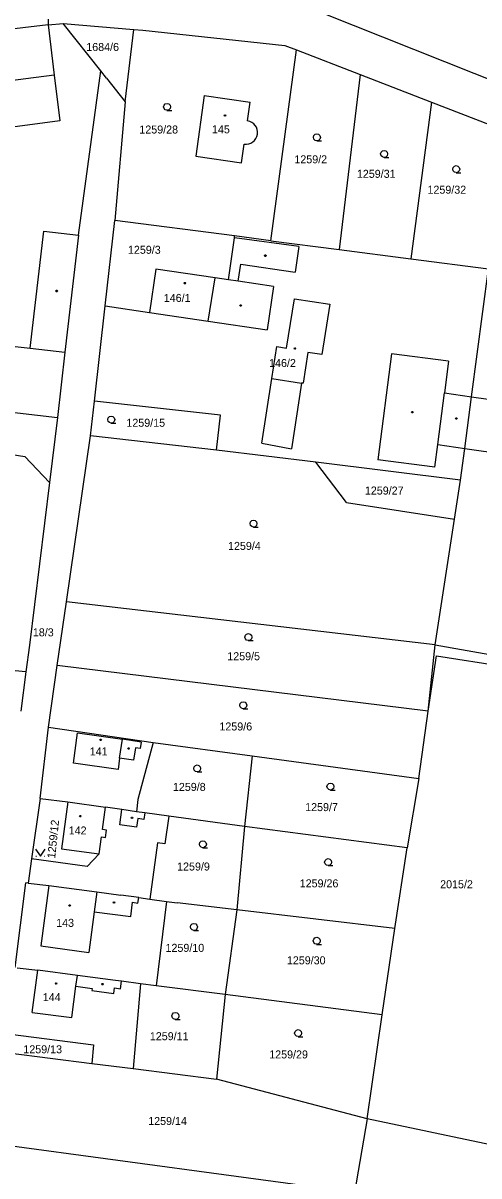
# Model space of a CAD drawing. Extents: x -802857 to -799647, y -1020285 to -1015884.
# Drawn here: x -801322.5 to -801225.7, y -1017885.2 to -1017640.2 of the extents above; entities that cross this region are included whole.
import ezdxf

# ---------------------------------------------------------------- set-up
doc = ezdxf.new("R2010")
doc.units = 0
for name, color, linetype in [('Default', 7, 'Continuous'), ('KN_HRANICE', 7, 'Continuous'), ('KN_KULTURY', 7, 'Continuous'), ('KN_PARCELY', 7, 'Continuous'), ('KN_SLUCKY', 7, 'Continuous')]:
    doc.layers.add(name, color=color, linetype=linetype)

# ---------------------------------------------------------------- blocks, each defined once
blk = doc.blocks.new('304')
at = {"layer": 'Default'}
blk.add_lwpolyline([(0, 0), (-0.38, 0.1), (-0.65, 0.37), (-0.75, 0.74), (-0.65, 1.11), (-0.38, 1.38), (-0.01, 1.48), (0.36, 1.38), (0.63, 1.11), (0.73, 0.73), (0.63, 0.35), (0.36, 0.08), (-0.02, -0.02), (0.98, -0.02)], dxfattribs=at)
blk = doc.blocks.new('314')
at = {"layer": 'Default'}
for p, q in [((-0.95, 0), (-0.85, 0)), ((0.85, 0), (0.95, 0))]:
    blk.add_line(p, q, dxfattribs=at)
blk.add_lwpolyline([(-1, 1.5), (0, 0), (1, 1.5)], dxfattribs=at)
blk = doc.blocks.new('402')
at = {"layer": 'Default'}
blk.add_lwpolyline([(0.09, 0.15), (0.18, 0), (0.09, -0.15), (-0.09, -0.15), (-0.18, 0), (-0.09, 0.15), (0.09, 0.15)], dxfattribs=at)

msp = doc.modelspace()

# ---------------------------------------------------------------- linework, layer by layer
at = {"layer": 'KN_HRANICE'}
for p, q in [((-801258.97, -1017638.08), (-801218.75, -1017654.12)), ((-801317.19, -1017639.44), (-801317.18, -1017640.62)), ((-801317.18, -1017640.62), (-801313.96, -1017640.33)), ((-801317.18, -1017640.62), (-801315.88, -1017651.33)), ((-801313.96, -1017640.33), (-801298.97, -1017641.6)), ((-801306.02, -1017650.39), (-801313.96, -1017640.33)), ((-801300.81, -1017657), (-801298.97, -1017641.6)), ((-801298.97, -1017641.6), (-801297.08, -1017641.76)), ((-801297.08, -1017641.76), (-801266.9, -1017645.01)), ((-801269.88, -1017686.48), (-801264.46, -1017645.95)), ((-801266.9, -1017645.01), (-801264.46, -1017645.95)), ((-801264.46, -1017645.95), (-801250.95, -1017651.18)), ((-801310.75, -1017685.3), (-801306.02, -1017650.39)), ((-801304.78, -1017651.96), (-801306.02, -1017650.39)), ((-801250.95, -1017651.18), (-801255.36, -1017688.35)), ((-801250.95, -1017651.18), (-801235.81, -1017657.04)), ((-801315.88, -1017651.33), (-801314.72, -1017661.03)), ((-801304.78, -1017651.96), (-801300.81, -1017657)), ((-801284.03, -1017655.6), (-801285.84, -1017668.53)), ((-801284.03, -1017655.6), (-801274.3, -1017657.02)), ((-801300.81, -1017657), (-801303.02, -1017682.18)), ((-801274.86, -1017661.01), (-801274.3, -1017657.02)), ((-801235.81, -1017657.04), (-801240.18, -1017690.3)), ((-801235.81, -1017657.04), (-801220.05, -1017663.14)), ((-801314.72, -1017661.03), (-801346.31, -1017665.23)), ((-801276.11, -1017669.95), (-801275.55, -1017665.96)), ((-801285.84, -1017668.53), (-801276.11, -1017669.95)), ((-801305.07, -1017700.32), (-801303.02, -1017682.18)), ((-801277.57, -1017685.48), (-801303.02, -1017682.18)), ((-801310.75, -1017685.3), (-801313.62, -1017710.16)), ((-801278.9, -1017694.79), (-801277.62, -1017685.88)), ((-801277.62, -1017685.88), (-801277.57, -1017685.48)), ((-801269.88, -1017686.48), (-801277.57, -1017685.48)), ((-801269.88, -1017686.48), (-801255.36, -1017688.35)), ((-801255.36, -1017688.35), (-801240.18, -1017690.3)), ((-801240.18, -1017690.3), (-801223.64, -1017692.43)), ((-801294.28, -1017692.51), (-801295.64, -1017701.71)), ((-801281.73, -1017694.37), (-801294.28, -1017692.51)), ((-801227.27, -1017719.62), (-801223.64, -1017692.43)), ((-801278.9, -1017694.79), (-801281.73, -1017694.37)), ((-801266.53, -1017709.31), (-801264.9, -1017698.8)), ((-801264.9, -1017698.8), (-801257.36, -1017699.97)), ((-801257.36, -1017699.97), (-801259.03, -1017710.68)), ((-801307.35, -1017720.56), (-801305.07, -1017700.32)), ((-801305.07, -1017700.32), (-801295.64, -1017701.71)), ((-801269.68, -1017715.75), (-801268.63, -1017708.99)), ((-801268.63, -1017708.99), (-801266.53, -1017709.31)), ((-801313.62, -1017710.16), (-801315.22, -1017724.02)), ((-801262.01, -1017710.22), (-801263.03, -1017716.78)), ((-801259.03, -1017710.68), (-801262.01, -1017710.22)), ((-801271.82, -1017729.5), (-801269.68, -1017715.75)), ((-801263.35, -1017716.73), (-801265.52, -1017730.72)), ((-801263.03, -1017716.78), (-801263.35, -1017716.73)), ((-801360.4, -1017718.86), (-801315.22, -1017724.02)), ((-801228.73, -1017730.61), (-801227.27, -1017719.62)), ((-801308.18, -1017727.92), (-801307.35, -1017720.56)), ((-801280.57, -1017723.56), (-801307.35, -1017720.56)), ((-801315.22, -1017724.02), (-801316.92, -1017737.87)), ((-801281.41, -1017730.95), (-801280.57, -1017723.56)), ((-801313.28, -1017763.19), (-801308.18, -1017727.92)), ((-801281.41, -1017730.95), (-801308.18, -1017727.92)), ((-801271.82, -1017729.5), (-801265.52, -1017730.72)), ((-801330.53, -1017731.02), (-801322.14, -1017732.32)), ((-801260.34, -1017733.55), (-801281.41, -1017730.95)), ((-801229.63, -1017737.33), (-801228.73, -1017730.61)), ((-801322.14, -1017732.32), (-801316.92, -1017737.87)), ((-801253.83, -1017742.07), (-801260.34, -1017733.55)), ((-801229.63, -1017737.33), (-801260.34, -1017733.55)), ((-801316.92, -1017737.87), (-801321.16, -1017772.38)), ((-801230.91, -1017745.67), (-801229.63, -1017737.33)), ((-801253.83, -1017742.07), (-801230.91, -1017745.67)), ((-801234.99, -1017772.37), (-801230.91, -1017745.67)), ((-801315.24, -1017776.75), (-801313.28, -1017763.19)), ((-801234.99, -1017772.37), (-801313.28, -1017763.19)), ((-801321.16, -1017772.38), (-801321.89, -1017778.08)), ((-801236.48, -1017786.43), (-801234.99, -1017772.37)), ((-801234.99, -1017772.37), (-801172.15, -1017783.49)), ((-801236.48, -1017786.43), (-801234.69, -1017774.68)), ((-801234.69, -1017774.68), (-801206.04, -1017779.14)), ((-801321.89, -1017778.08), (-801333.83, -1017776.95)), ((-801321.89, -1017778.08), (-801322.97, -1017786.42)), ((-801317.13, -1017789.83), (-801315.24, -1017776.75)), ((-801236.48, -1017786.43), (-801315.24, -1017776.75)), ((-801238.47, -1017800.75), (-801236.48, -1017786.43)), ((-801318.85, -1017804.96), (-801317.13, -1017789.83)), ((-801317.13, -1017789.83), (-801294.9, -1017793.05)), ((-801294.9, -1017793.05), (-801298.1, -1017805.2)), ((-801294.9, -1017793.05), (-801273.85, -1017795.89)), ((-801273.85, -1017795.89), (-801275.49, -1017810.94)), ((-801273.85, -1017795.89), (-801238.47, -1017800.75)), ((-801238.47, -1017800.75), (-801240.97, -1017815.46)), ((-801318.85, -1017804.96), (-801320.69, -1017817.83)), ((-801318.85, -1017804.96), (-801313, -1017805.71)), ((-801298.1, -1017805.2), (-801298.41, -1017807.79)), ((-801313, -1017805.71), (-801314.37, -1017815.67)), ((-801313, -1017805.71), (-801305, -1017806.85)), ((-801301.51, -1017807.35), (-801305, -1017806.85)), ((-801298.41, -1017807.79), (-801301.51, -1017807.35)), ((-801296.65, -1017808.02), (-801298.41, -1017807.79)), ((-801291.57, -1017808.72), (-801296.65, -1017808.02)), ((-801291.57, -1017808.72), (-801292.38, -1017814.62)), ((-801275.49, -1017810.94), (-801291.57, -1017808.72)), ((-801275.49, -1017810.94), (-801277.13, -1017828.65)), ((-801240.97, -1017815.46), (-801275.49, -1017810.94)), ((-801293.96, -1017814.4), (-801295.6, -1017826.35)), ((-801292.38, -1017814.62), (-801293.96, -1017814.4)), ((-801314.37, -1017815.67), (-801306.37, -1017816.77)), ((-801306.37, -1017816.77), (-801308.92, -1017819.41)), ((-801243.53, -1017832.62), (-801240.97, -1017815.46)), ((-801320.69, -1017817.83), (-801321.42, -1017822.98)), ((-801308.92, -1017819.41), (-801320.69, -1017817.83)), ((-801324.21, -1017840.9), (-801321.92, -1017822.92)), ((-801321.42, -1017822.98), (-801321.92, -1017822.92)), ((-801321.42, -1017822.98), (-801317, -1017823.5)), ((-801317, -1017823.5), (-801306.82, -1017824.84)), ((-801306.82, -1017824.84), (-801301.75, -1017825.51)), ((-801297.95, -1017826.03), (-801301.75, -1017825.51)), ((-801297.95, -1017826.03), (-801295.6, -1017826.35)), ((-801295.6, -1017826.35), (-801292.03, -1017826.83)), ((-801292.03, -1017826.83), (-801294.26, -1017844.75)), ((-801292.03, -1017826.83), (-801289.77, -1017827.14)), ((-801277.13, -1017828.65), (-801289.77, -1017827.14)), ((-801277.13, -1017828.65), (-801279.58, -1017846.65)), ((-801243.53, -1017832.62), (-801277.13, -1017828.65)), ((-801246.26, -1017850.96), (-801243.53, -1017832.62)), ((-801323.76, -1017840.95), (-801319.39, -1017841.48)), ((-801310.96, -1017842.58), (-801319.39, -1017841.48)), ((-801302.87, -1017843.64), (-801310.96, -1017842.58)), ((-801301.57, -1017843.81), (-801302.87, -1017843.64)), ((-801297.53, -1017844.33), (-801301.57, -1017843.81)), ((-801297.53, -1017844.33), (-801299.15, -1017862.36)), ((-801294.26, -1017844.75), (-801297.53, -1017844.33)), ((-801279.58, -1017846.65), (-801294.26, -1017844.75)), ((-801279.58, -1017846.65), (-801281.41, -1017864.6)), ((-801246.26, -1017850.96), (-801279.58, -1017846.65)), ((-801249.45, -1017873.01), (-801246.26, -1017850.96)), ((-801325.19, -1017855.03), (-801307.53, -1017857.34)), ((-801325.59, -1017859.01), (-801307.91, -1017861.25)), ((-801307.53, -1017857.34), (-801307.91, -1017861.25)), ((-801307.91, -1017861.25), (-801299.15, -1017862.36)), ((-801299.15, -1017862.36), (-801281.41, -1017864.6)), ((-801249.45, -1017873.01), (-801281.41, -1017864.6)), ((-801249.45, -1017873.01), (-801252.11, -1017888.65)), ((-801223.26, -1017878.53), (-801249.45, -1017873.01)), ((-801252.11, -1017888.65), (-801327.56, -1017878.51))]:
    msp.add_line(p, q, dxfattribs=at)
msp.add_arc((-801275.2, -1017663.49), 2.5, 262.0645, 82.0644, dxfattribs=at)
at = {"layer": 'KN_SLUCKY'}
for p, q in [((-801317.18, -1017640.62), (-801334.53, -1017642.7)), ((-801315.88, -1017651.33), (-801346.88, -1017655.22)), ((-801320.96, -1017709.32), (-801318.12, -1017684.46)), ((-801318.12, -1017684.46), (-801310.75, -1017685.3)), ((-801263.92, -1017687.68), (-801277.62, -1017685.88)), ((-801263.92, -1017687.68), (-801264.71, -1017693.15)), ((-801276.81, -1017695.1), (-801276.28, -1017691.44)), ((-801276.28, -1017691.44), (-801264.71, -1017693.15)), ((-801283.17, -1017703.56), (-801281.73, -1017694.37)), ((-801276.81, -1017695.1), (-801278.9, -1017694.79)), ((-801269.34, -1017696.2), (-801276.81, -1017695.1)), ((-801269.34, -1017696.2), (-801270.7, -1017705.4)), ((-801295.64, -1017701.71), (-801283.17, -1017703.56)), ((-801283.17, -1017703.56), (-801270.7, -1017705.4)), ((-801335.42, -1017707.67), (-801320.96, -1017709.32)), ((-801320.96, -1017709.32), (-801313.62, -1017710.16)), ((-801244.25, -1017710.49), (-801247.15, -1017733)), ((-801232.15, -1017712.05), (-801244.25, -1017710.49)), ((-801232.15, -1017712.05), (-801233.02, -1017718.8)), ((-801269.68, -1017715.75), (-801263.35, -1017716.73)), ((-801234.44, -1017729.8), (-801233.02, -1017718.8)), ((-801233.02, -1017718.8), (-801227.27, -1017719.62)), ((-801227.27, -1017719.62), (-801204.41, -1017722.86)), ((-801235.05, -1017734.56), (-801234.44, -1017729.8)), ((-801234.44, -1017729.8), (-801228.73, -1017730.61)), ((-801228.73, -1017730.61), (-801206.81, -1017733.72)), ((-801235.05, -1017734.56), (-801247.15, -1017733)), ((-801311.81, -1017797.47), (-801310.92, -1017791.04)), ((-801310.92, -1017791.04), (-801301.41, -1017792.41)), ((-801301.99, -1017796.42), (-801301.41, -1017792.41)), ((-801297.4, -1017792.99), (-801301.41, -1017792.41)), ((-801297.4, -1017792.99), (-801297.6, -1017794.37)), ((-801298.64, -1017794.22), (-801299.02, -1017796.85)), ((-801297.6, -1017794.37), (-801298.64, -1017794.22)), ((-801302.34, -1017798.84), (-801311.81, -1017797.47)), ((-801301.99, -1017796.42), (-801302.34, -1017798.84)), ((-801299.02, -1017796.85), (-801301.99, -1017796.42)), ((-801305.65, -1017811.57), (-801305, -1017806.85)), ((-801301.96, -1017810.55), (-801301.51, -1017807.35)), ((-801298.14, -1017809.22), (-801298.4, -1017811.06)), ((-801296.85, -1017809.41), (-801298.14, -1017809.22)), ((-801296.65, -1017808.02), (-801296.85, -1017809.41)), ((-801304.76, -1017811.69), (-801305.65, -1017811.57)), ((-801304.98, -1017813.28), (-801304.76, -1017811.69)), ((-801298.4, -1017811.06), (-801301.96, -1017810.55)), ((-801306.37, -1017816.77), (-801305.87, -1017813.15)), ((-801305.87, -1017813.15), (-801304.98, -1017813.28)), ((-801317, -1017823.5), (-801318.7, -1017836.28)), ((-801306.82, -1017824.84), (-801307.38, -1017829.03)), ((-801299.65, -1017830.06), (-801299.25, -1017827.03)), ((-801299.25, -1017827.03), (-801298.11, -1017827.19)), ((-801298.11, -1017827.19), (-801297.95, -1017826.03)), ((-801307.38, -1017829.03), (-801308.53, -1017837.68)), ((-801307.38, -1017829.03), (-801299.65, -1017830.06)), ((-801318.7, -1017836.28), (-801308.53, -1017837.68)), ((-801320.6, -1017850.42), (-801319.39, -1017841.48)), ((-801311.27, -1017844.87), (-801310.96, -1017842.58)), ((-801301.79, -1017845.4), (-801301.57, -1017843.81)), ((-801312.17, -1017851.52), (-801311.27, -1017844.87)), ((-801311.27, -1017844.87), (-801307.84, -1017845.34)), ((-801307.84, -1017845.34), (-801307.9, -1017845.78)), ((-801307.9, -1017845.78), (-801303.25, -1017846.42)), ((-801303.25, -1017846.42), (-801303.09, -1017845.22)), ((-801303.09, -1017845.22), (-801301.79, -1017845.4)), ((-801320.6, -1017850.42), (-801312.17, -1017851.52))]:
    msp.add_line(p, q, dxfattribs=at)

# ---------------------------------------------------------------- block references
at = {"layer": 'KN_KULTURY'}
for name, p in [('304', (-801291.92, -1017658.78)), ('402', (-801279.61, -1017659.89)), ('304', (-801260.1, -1017665.26)), ('304', (-801245.82, -1017668.79)), ('304', (-801230.52, -1017672.02)), ('402', (-801271.07, -1017689.66)), ('402', (-801315.35, -1017697.17)), ('402', (-801288.15, -1017695.53)), ('402', (-801276.28, -1017700.24)), ('402', (-801264.78, -1017709.37)), ('304', (-801303.77, -1017725.23)), ('402', (-801239.85, -1017722.89)), ('402', (-801230.51, -1017724.25)), ('304', (-801273.56, -1017747.32)), ('304', (-801274.65, -1017771.42)), ('304', (-801275.73, -1017785.9)), ('402', (-801306.02, -1017792.52)), ('402', (-801300.1, -1017794.38)), ('304', (-801285.52, -1017799.33)), ('304', (-801257.22, -1017803.18)), ('402', (-801310.37, -1017808.73)), ('402', (-801299.38, -1017809.08)), ('304', (-801284.3, -1017815.43)), ('314', (-801318.83, -1017817.23)), ('304', (-801257.72, -1017819.23)), ('402', (-801303.19, -1017827.05)), ('402', (-801312.59, -1017827.71)), ('304', (-801286.21, -1017833)), ('304', (-801260.14, -1017835.95)), ('402', (-801315.48, -1017844.29)), ('402', (-801305.63, -1017844.4)), ('304', (-801290.15, -1017851.92)), ('304', (-801264.08, -1017855.57))]:
    msp.add_blockref(name, p, dxfattribs=at)

# ---------------------------------------------------------------- texts
at = {"layer": 'KN_PARCELY'}
for s, p in [('1684/6', (-801309.08, -1017646.18)), ('1259/28', (-801297.81, -1017663.71)), ('145', (-801282.39, -1017663.67)), ('1259/2', (-801264.89, -1017670.04)), ('1259/31', (-801251.62, -1017673.12)), ('1259/32', (-801236.63, -1017676.5)), ('1259/3', (-801300.23, -1017689.26)), ('146/1', (-801292.62, -1017699.49)), ('146/2', (-801270.26, -1017713.32)), ('1259/15', (-801300.56, -1017726.01)), ('1259/27', (-801249.92, -1017740.41)), ('1259/4', (-801278.98, -1017752.17)), ('18/3', (-801320.42, -1017770.53)), ('1259/5', (-801279.14, -1017775.61)), ('1259/6', (-801280.81, -1017790.53)), ('141', (-801308.34, -1017795.82)), ('1259/8', (-801290.68, -1017803.37)), ('1259/7', (-801262.6, -1017807.66)), ('142', (-801312.81, -1017812.63)), ('1259/9', (-801289.79, -1017820.28)), ('1259/26', (-801263.76, -1017823.86)), ('2015/2', (-801233.94, -1017824.05)), ('143', (-801315.47, -1017832.25)), ('1259/10', (-801292.25, -1017837.56)), ('1259/30', (-801266.48, -1017840.21)), ('144', (-801318.31, -1017848.03)), ('1259/11', (-801295.58, -1017856.33)), ('1259/13', (-801322.44, -1017859.11)), ('1259/29', (-801270.23, -1017860.2)), ('1259/14', (-801295.93, -1017874.35))]:
    msp.add_text(s, height=1.7, dxfattribs=at).set_placement(p)
msp.add_text('1259/12', height=1.7, rotation=84.053, dxfattribs=at).set_placement((-801315.69, -1017817.77))

doc.saveas('drawing.dxf')
